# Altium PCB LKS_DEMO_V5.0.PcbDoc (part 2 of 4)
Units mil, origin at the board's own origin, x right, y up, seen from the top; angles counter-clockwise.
Board outline 5414.8 x 3354.56 mil, 2 copper layers (Top Layer, Bottom Layer); 131 components, 85 nets, 355 pads, 272 vias.
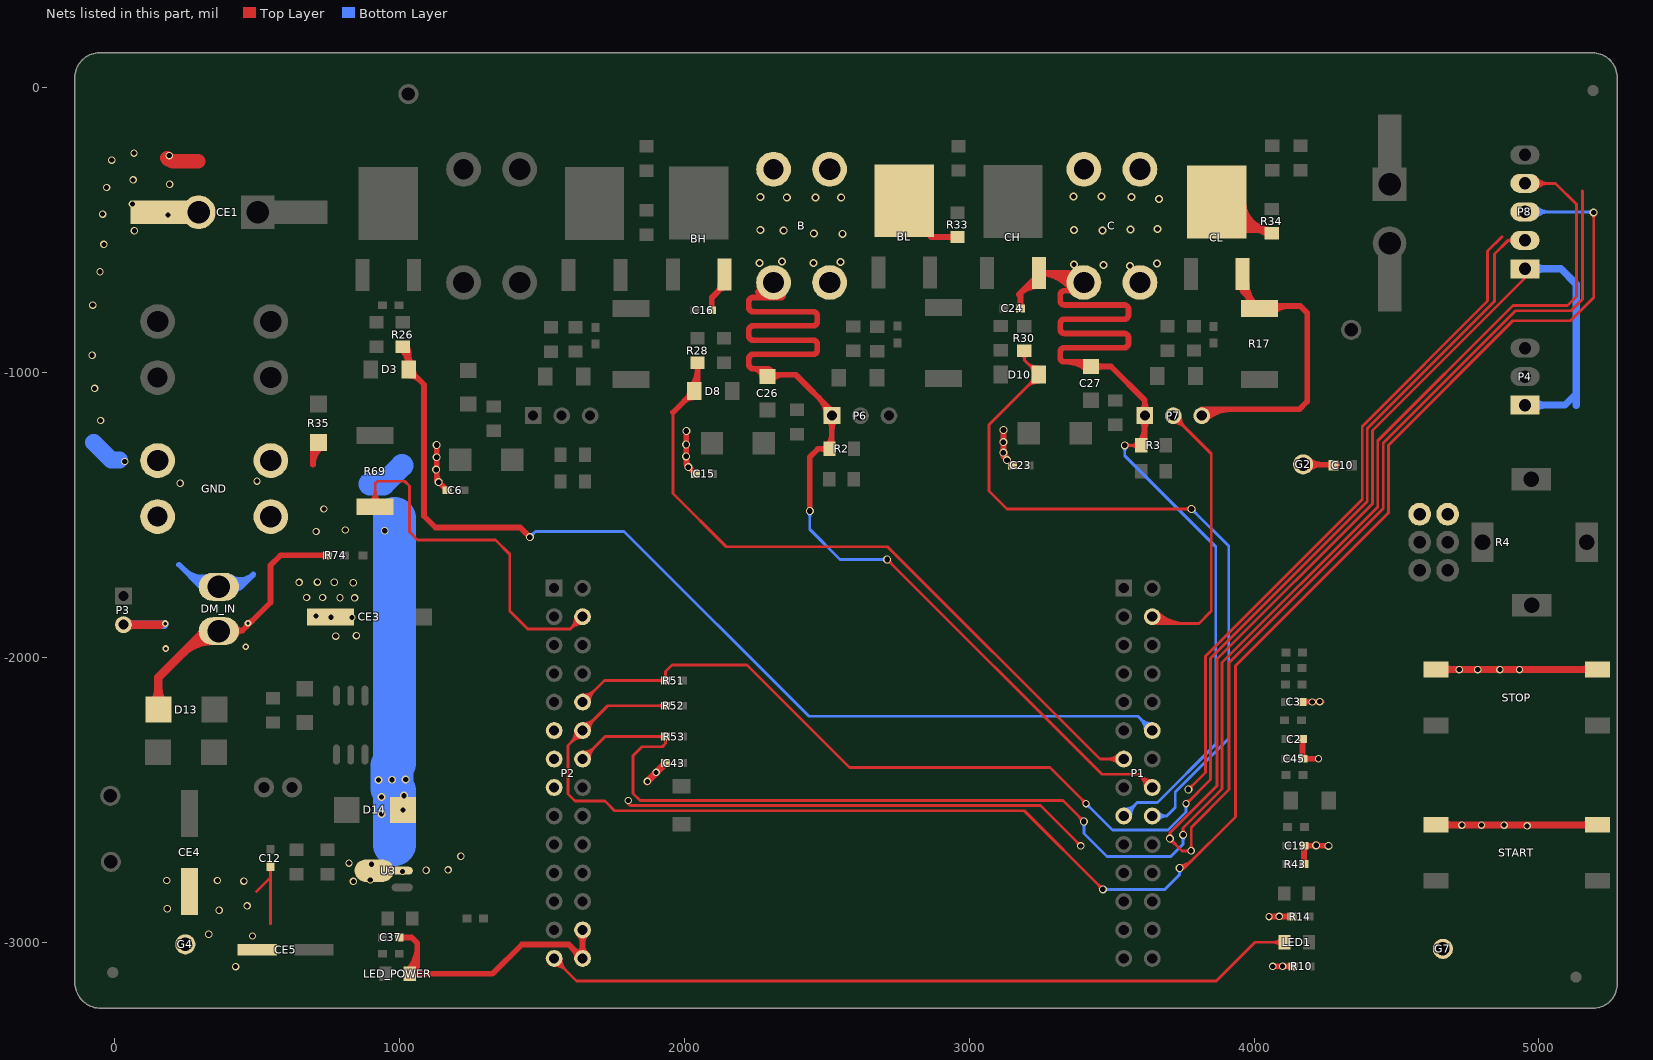
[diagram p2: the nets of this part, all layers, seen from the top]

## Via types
v1: diameter 26, hole 18, Top Layer to Bottom Layer, 117 vias
v2: diameter 28, hole 20, Top Layer to Bottom Layer, 77 vias
v3: diameter 28, hole 18, Top Layer to Bottom Layer, 73 vias
v4: diameter 23.62, hole 11.81, Top Layer to Bottom Layer, 5 vias

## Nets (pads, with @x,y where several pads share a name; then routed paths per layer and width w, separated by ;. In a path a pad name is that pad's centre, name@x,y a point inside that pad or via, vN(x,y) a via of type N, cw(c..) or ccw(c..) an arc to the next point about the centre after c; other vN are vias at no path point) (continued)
BX: B.1 BH.3 BL.2 C16.2 C26.2 P1.22 P6.1 R2.2 R33.2 | length 5651.7
  Top Layer w10: v2(2711.53,-1656.28) 3465.28,-2410.04 3595.47,-2410.04 P1.22@3642.25,-2456.82 ; 2726.89,-1671.64 ccw(c2711.53,-1687.01) 2711.53,-1665.28 cw(c2711.53,-1687.01) 2726.89,-1671.64 ; 2726.89,-1671.64 cw(c2742.25,-1656.28) 2720.53,-1656.28 ccw(c2742.25,-1656.28) 2726.89,-1671.64 ; 3600.38,-2414.94 ccw(c3642.25,-2373.07) 3642.25,-2432.29 cw(c3642.25,-2373.07) 3600.38,-2414.94 ; 3600.38,-2414.94 cw(c3558.51,-2456.82) 3617.72,-2456.82 ccw(c3558.51,-2456.82) 3600.38,-2414.94 ; 3617.45,-2432.02 ccw(c3642.25,-2407.22) 3642.25,-2442.29 cw(c3642.25,-2407.22) 3617.45,-2432.02 ; 3617.45,-2432.02 cw(c3592.65,-2456.82) 3627.72,-2456.82 ccw(c3592.65,-2456.82) 3617.45,-2432.02
  Top Layer w20: C16.2@2095.76,-779.93 2095.76,-737.17 BH.3@2142.44,-690.49 ; 2256.72,-716.82 2275.97,-736.07 ; C26.2@2283.73,-1030.78 2306.96,-1007.55 2390.76,-1007.55 2517.75,-1134.54 P6.1@2517.75,-1146.43 ; C26.2@2292.27,-1001.77 2276.58,-986.07 2240.96,-986.07 ; B.1@2345.96,-729.82 cw(c2339.71,-729.82) 2339.71,-736.07 2275.97,-736.07 ; v2(2439.84,-1486.25) 2439.84,-1296.61 2468.64,-1267.81 R2.2@2509.31,-1267.81 ; R2.2@2517.24,-1252.66 P6.1@2517.24,-1145.92 ; BL.2@2818.05,-476.55 2865.7,-524.2 R33.2@2958.78,-524.2 ; 2240.96,-986.07 cw(c2240.96,-971.07) 2225.96,-971.07 2225.96,-951.07 cw(c2240.96,-951.07) 2240.96,-936.07 2450.96,-936.07 ccw(c2450.96,-921.07) 2465.96,-921.07 2465.96,-901.07 ccw(c2450.96,-901.07) 2450.96,-886.07 2240.96,-886.07 cw(c2240.96,-871.07) 2225.96,-871.07 2225.96,-851.07 cw(c2240.96,-851.07) 2240.96,-836.07 2450.96,-836.07 ccw(c2450.96,-821.07) 2465.96,-821.07 2465.96,-801.07 ccw(c2450.96,-801.07) 2450.96,-786.07 2240.96,-786.07 cw(c2240.96,-771.07) 2225.96,-771.07 2225.96,-751.07 cw(c2240.96,-751.07) 2240.96,-736.07 2275.97,-736.07 ; 2240.96,-986.07 cw(c2240.96,-1018.55) 2273.27,-1015.24 ccw(c2240.96,-1018.55) 2240.96,-986.07 ; 2481.18,-1267.81 ccw(c2481.18,-1239.68) 2501.07,-1259.57 cw(c2481.18,-1239.68) 2481.18,-1267.81 ; 2481.18,-1267.81 cw(c2481.18,-1295.95) 2501.07,-1276.05 ccw(c2481.18,-1295.95) 2481.18,-1267.81 ; 2927.3,-524.2 ccw(c2927.3,-496.07) 2947.2,-515.96 cw(c2927.3,-496.07) 2927.3,-524.2 ; 2927.3,-524.2 cw(c2927.3,-552.33) 2947.2,-532.44 ccw(c2927.3,-552.33) 2927.3,-524.2 ; 2112.38,-720.55 ccw(c2079.48,-687.65) 2126.01,-687.65 cw(c2079.48,-687.65) 2112.38,-720.55 ; BH.3@2123.65,-709.29 cw(c2140.62,-726.26) 2140.62,-702.26 ccw(c2140.62,-726.26) BH.3@2123.65,-709.29 ; 2263.12,-986.07 cw(c2263.12,-1016.28) 2293.17,-1013.2 ccw(c2263.12,-1016.28) 2263.12,-986.07 ; 2285.27,-986.07 cw(c2285.27,-1014.01) 2313.06,-1011.16 ccw(c2285.27,-1014.01) 2285.27,-986.07 ; C26.2@2305.42,-1025.27 cw(c2348.2,-1068.06) 2348.2,-1007.55 ccw(c2348.2,-1068.06) C26.2@2305.42,-1025.27 ; 2472.61,-1089.39 cw(c2410.76,-1151.24) 2498.22,-1151.24 ccw(c2410.76,-1151.24) 2472.61,-1089.39 ; R2.2@2501.07,-1256.23 ccw(c2462.03,-1217.19) 2517.24,-1217.19 cw(c2462.03,-1217.19) R2.2@2501.07,-1256.23 ; P6.1@2503.94,-1165.05 cw(c2471.83,-1197.16) 2517.24,-1197.16 ccw(c2471.83,-1197.16) P6.1@2503.94,-1165.05 ; P6.1@2506.75,-1123.54 cw(c2479.05,-1151.24) 2518.22,-1151.24 ccw(c2479.05,-1151.24) P6.1@2506.75,-1123.54 ; 2517.24,-1199.61 cw(c2566.12,-1199.61) 2531.56,-1165.05 ccw(c2566.12,-1199.61) 2517.24,-1199.61
  Top Layer w30: BL.2@2771.14,-396.91 BL.2@2843.26,-324.79
  Bottom Layer w10: v2(2439.84,-1486.25) 2439.84,-1549.97 2546.15,-1656.28 v2(2711.53,-1656.28) ; 2439.84,-1507.98 ccw(c2418.11,-1507.98) 2433.48,-1492.61 cw(c2418.11,-1507.98) 2439.84,-1507.98 ; 2439.84,-1507.98 cw(c2461.57,-1507.98) 2446.2,-1492.61 ccw(c2461.57,-1507.98) 2439.84,-1507.98 ; 2689.8,-1656.28 ccw(c2689.8,-1634.55) 2705.16,-1649.92 cw(c2689.8,-1634.55) 2689.8,-1656.28 ; 2689.8,-1656.28 cw(c2689.8,-1678.01) 2705.16,-1662.64 ccw(c2689.8,-1678.01) 2689.8,-1656.28
  other v3: 2453.04,-615.74 2262.77,-614.91 2548.36,-611.49 2341.84,-609.97 2554.35,-512.78 2453.86,-511.13 2348.43,-501.25 2266.06,-499.6 2359.14,-385.93 2459.63,-385.11 2550.23,-385.11 2266.06,-383.46
CI: CL.3 P7.3 R17.1 | length 1960.4
  Top Layer w20: P7.3@3816.05,-1129.25 4158.12,-1129.25 4185.85,-1101.52 4185.85,-790.19 4161.78,-766.12 R17.1@4035,-766.12 ; CL.3@3959.59,-653.34 3959.59,-714.63 ; R17.1@4018.89,-773.93 3959.59,-714.63 ; CL.3@3950.65,-696.38 cw(c3936.51,-714.63) 3959.59,-714.63 ; CL.3@3950.65,-696.38 cw(c3936.51,-714.63) 3959.59,-714.63 ; CL.3@3950.65,-696.38 cw(c3936.51,-714.63) 3959.59,-714.63 ; CL.3@3950.65,-696.38 cw(c3936.51,-714.63) 3959.59,-714.63 ; 3959.59,-714.63 cw(c3982.67,-714.63) CL.3@3968.54,-696.38 ; 3959.59,-714.63 cw(c3982.67,-714.63) CL.3@3968.54,-696.38 ; 3959.59,-714.63 cw(c3982.67,-714.63) CL.3@3968.54,-696.38 ; 3959.59,-714.63 cw(c3982.67,-714.63) CL.3@3968.54,-696.38 ; P7.3@3815.72,-1150.9 cw(c3867.98,-1203.17) 3867.98,-1129.25 ccw(c3867.98,-1203.17) P7.3@3815.72,-1150.9 ; P7.3@3829.86,-1165.05 cw(c3916.27,-1251.46) 3916.27,-1129.25 ccw(c3916.27,-1251.46) P7.3@3829.86,-1165.05 ; CL.3@3954.2,-684.73 ccw(c4010.73,-685.8) 3970.75,-725.78 cw(c4010.73,-685.8) CL.3@3954.2,-684.73 ; 3968.31,-723.35 cw(c3927.85,-763.81) 3984.04,-774.61 ccw(c3927.85,-763.81) 3968.31,-723.35 ; CL.3@3974.2,-685.11 ccw(c4075.98,-687.04) 4003.99,-759.03 cw(c4075.98,-687.04) CL.3@3974.2,-685.11 ; R17.1@4068.26,-788.33 cw(c4121.87,-841.94) 4121.87,-766.12 ccw(c4121.87,-841.94) R17.1@4068.26,-788.33
CP: P1.16 P7.2 | length 2028.1
  Top Layer w10: P1.16@3642.25,-1856.82 3666.39,-1880.96 3806.07,-1880.96 3849.41,-1837.62 3849.41,-1284.87 3716.05,-1151.52 P7.2@3716.05,-1129.25 ; P1.16@3631.31,-1867.76 ccw(c3663.18,-1835.89) 3663.18,-1880.96 cw(c3663.18,-1835.89) P1.16@3631.31,-1867.76 ; P1.16@3638.38,-1860.69 ccw(c3687.32,-1811.75) 3687.32,-1880.96 cw(c3687.32,-1811.75) P1.16@3638.38,-1860.69 ; P1.16@3645.45,-1853.61 ccw(c3711.46,-1787.6) 3711.46,-1880.96 cw(c3711.46,-1787.6) P1.16@3645.45,-1853.61 ; P1.16@3652.52,-1846.54 ccw(c3735.6,-1763.46) 3735.6,-1880.96 cw(c3735.6,-1763.46) P1.16@3652.52,-1846.54 ; P1.16@3659.59,-1839.47 ccw(c3759.75,-1739.32) 3759.75,-1880.96 cw(c3759.75,-1739.32) P1.16@3659.59,-1839.47 ; P7.2@3716.05,-1175.77 cw(c3716.05,-1234.31) 3757.45,-1192.91 ccw(c3716.05,-1234.31) P7.2@3716.05,-1175.77 ; P7.2@3716.05,-1165.77 cw(c3716.05,-1200.16) 3740.37,-1175.84 ccw(c3716.05,-1200.16) P7.2@3716.05,-1165.77 ; P7.2@3730.58,-1151.24 ccw(c3766.32,-1151.24) 3741.05,-1176.51 cw(c3766.32,-1151.24) P7.2@3730.58,-1151.24 ; P7.2@3740.58,-1151.24 ccw(c3800.47,-1151.24) 3758.12,-1193.59 cw(c3800.47,-1151.24) P7.2@3740.58,-1151.24
CX: C24.2 C27.2 C.1 CH.3 CL.2 P1.9 P7.1 R3.2 R34.2 | length 7899.2
  Top Layer w10: v2@3545.76,-1255.52 R3.2@3603.88,-1255.52 ; 3563.68,-1255.52 ccw(c3563.68,-1215.31) 3592.11,-1243.74 cw(c3563.68,-1215.31) 3563.68,-1255.52 ; 3563.68,-1255.52 cw(c3563.68,-1295.72) 3592.11,-1267.29 ccw(c3563.68,-1295.72) 3563.68,-1255.52 ; v2@3552.04,-1261.8 cw(c3567.2,-1276.96) 3567.2,-1255.52 ccw(c3567.2,-1276.96) v2@3552.04,-1261.8 ; v2@3552.04,-1249.07 ccw(c3567.6,-1233.51) 3567.6,-1255.52 cw(c3567.6,-1233.51) v2@3552.04,-1249.07
  Top Layer w20: C24.2@3179.62,-774.76 3179.62,-719.71 CH.3@3244.29,-655.03 ; C.1@3407.81,-708.51 3350.03,-650.72 CH.3@3243.88,-650.72 ; C27.2@3427.06,-978.99 3497.71,-978.99 3616.05,-1097.32 P7.1@3616.05,-1151.24 ; C27.2@3431.28,-962.46 3334.05,-962.46 cw(c3334.05,-947.46) 3319.05,-947.46 3319.05,-927.46 cw(c3334.05,-927.46) 3334.05,-912.46 3544.05,-912.46 ccw(c3544.05,-897.46) 3559.05,-897.46 3559.05,-877.46 ccw(c3544.05,-877.46) 3544.05,-862.46 3334.05,-862.46 cw(c3334.05,-847.46) 3319.05,-847.46 3319.05,-827.46 cw(c3334.05,-827.46) 3334.05,-812.46 3544.05,-812.46 ccw(c3544.05,-797.46) 3559.05,-797.46 3559.05,-777.46 ccw(c3544.05,-777.46) 3544.05,-762.46 3334.05,-762.46 cw(c3334.05,-747.46) 3319.05,-747.46 3319.05,-727.46 cw(c3334.05,-727.46) 3334.05,-712.46 3430.58,-712.46 ccw(c3430.58,-704) C.1@3439.04,-704 ; R3.2@3614.91,-1254.73 P7.1@3614.91,-1128.61 ; CL.2@3869.04,-401.37 3967.82,-500.15 R34.2@4064.65,-500.15 ; CH.3@3243.88,-650.72 cw(c3243.89,-790.89) 3360,-712.38 ccw(c3243.89,-790.89) CH.3@3243.88,-650.72 ; 3279.14,-650.72 ccw(c3279.14,-685.99) 3254.21,-661.05 cw(c3279.14,-685.99) 3279.14,-650.72 ; 3279.14,-650.72 cw(c3279.14,-615.46) 3254.21,-640.4 ccw(c3279.14,-615.46) 3279.14,-650.72 ; 3469.04,-978.99 ccw(c3469.04,-1019) 3440.74,-990.71 cw(c3469.04,-1019) 3469.04,-978.99 ; 3469.04,-978.99 cw(c3469.04,-938.97) 3440.74,-967.27 ccw(c3469.04,-938.97) 3469.04,-978.99 ; 3616.05,-1104.09 ccw(c3663.19,-1104.09) 3629.86,-1137.43 cw(c3663.19,-1104.09) 3616.05,-1104.09 ; 3616.05,-1104.09 cw(c3568.91,-1104.09) 3602.24,-1137.43 ccw(c3568.91,-1104.09) 3616.05,-1104.09 ; R34.2@4064.64,-500.15 cw(c4064.64,-396.87) 3962.41,-411.57 ccw(c4064.64,-396.87) R34.2@4064.64,-500.15 ; 3173.24,-726.09 cw(c3243.88,-796.73) 3243.88,-696.83 ccw(c3243.88,-796.73) 3173.24,-726.09 ; 3207.38,-691.95 cw(c3243.88,-728.45) 3243.88,-676.83 ccw(c3243.88,-728.45) 3207.38,-691.95 ; CH.3@3241.52,-657.8 cw(c3243.88,-660.16) 3243.88,-656.83 ccw(c3243.88,-660.16) CH.3@3241.52,-657.8 ; 3281.56,-650.72 cw(c3281.56,-765.42) 3376.57,-701.17 ccw(c3281.56,-765.42) 3281.56,-650.72 ; 3319.22,-650.72 cw(c3319.22,-739.95) 3393.14,-689.97 ccw(c3319.22,-739.95) 3319.22,-650.72 ; 3345.18,-962.46 cw(c3345.18,-1058.9) 3413.37,-990.71 ccw(c3345.18,-1058.9) 3345.18,-962.46 ; 3348.3,-712.46 cw(c3348.3,-737.77) 3366.19,-719.87 ccw(c3348.3,-737.77) 3348.3,-712.46 ; 3393.46,-962.46 cw(c3393.46,-1010.61) 3427.51,-976.57 ccw(c3393.46,-1010.61) 3393.46,-962.46 ; R3.2@3595.64,-1243.93 ccw(c3549.14,-1197.43) 3614.91,-1197.43 cw(c3549.14,-1197.43) R3.2@3595.64,-1243.93 ; P7.1@3602.24,-1165.05 cw(c3571.67,-1195.62) 3614.91,-1195.62 ccw(c3571.67,-1195.62) P7.1@3602.24,-1165.05 ; 3614.91,-1201.15 cw(c3665.96,-1201.15) 3629.86,-1165.05 ccw(c3665.96,-1201.15) 3614.91,-1201.15 ; CL.2@3883.23,-422.95 ccw(c3972.32,-410.14) 3972.32,-500.15 cw(c3972.32,-410.14) CL.2@3883.23,-422.95 ; CL.2@3903.02,-420.1 ccw(c3995.4,-406.82) 3995.4,-500.15 cw(c3995.4,-406.82) CL.2@3903.02,-420.1 ; CL.2@3922.82,-417.26 ccw(c4018.48,-403.5) 4018.48,-500.15 cw(c4018.48,-403.5) CL.2@3922.82,-417.26 ; CL.2@3942.61,-414.41 ccw(c4041.56,-400.18) 4041.56,-500.15 cw(c4041.56,-400.18) CL.2@3942.61,-414.41 ; 4003.57,-500.15 cw(c4003.57,-566.15) 4050.23,-519.48 ccw(c4003.57,-566.15) 4003.57,-500.15
  Bottom Layer w10: P1.9@3542.25,-2556.82 3589.53,-2509.53 3660.12,-2509.53 3865.01,-2304.65 3865.01,-1611.21 3545.66,-1291.87 v2@3545.66,-1255.42 ; 3567.05,-2532.02 ccw(c3591.85,-2556.82) 3556.78,-2556.82 cw(c3591.85,-2556.82) 3567.05,-2532.02 ; 3567.05,-2532.02 cw(c3542.25,-2507.22) 3542.25,-2542.29 ccw(c3542.25,-2507.22) 3567.05,-2532.02 ; 3584.12,-2514.94 ccw(c3625.99,-2556.82) 3566.78,-2556.82 cw(c3625.99,-2556.82) 3584.12,-2514.94 ; 3584.12,-2514.94 cw(c3542.25,-2473.07) 3542.25,-2532.29 ccw(c3542.25,-2473.07) 3584.12,-2514.94 ; v2@3539.31,-1261.8 cw(c3523.97,-1277.14) 3545.66,-1277.14 ccw(c3523.97,-1277.14) v2@3539.31,-1261.8 ; 3545.66,-1277.18 cw(c3567.42,-1277.18) 3552.04,-1261.8 ccw(c3567.42,-1277.18) 3545.66,-1277.18
  other v2: 3545.67,-1255.43
  other v3: 3564.36,-625.82 3471.16,-622.37 3367.61,-620.65 3658.66,-616.83 3467.71,-501.56 3367.61,-499.84 3566.09,-498.11 3661.01,-496.39 3666.19,-391.11 3569.54,-384.21 3365.89,-382.48 3464.26,-382.48
DM_IN: D13.1 DM_IN.1 P3.2 R74.1 | length 2236.4
  Top Layer w20: DM_IN.1@316.98,-1905.81 447.95,-1905.81 ; R74.1@746.62,-1641.8 581.53,-1641.8 546.73,-1676.6 546.73,-1807.04 447.95,-1905.81 ; 447.95,-1905.81 ccw(c447.95,-1932.18) 423.45,-1922.44 cw(c447.95,-1932.18) 447.95,-1905.81 ; 447.95,-1905.81 cw(c447.95,-1876.37) 421.82,-1889.92 ccw(c447.95,-1876.37) 447.95,-1905.81 ; 460.08,-1893.69 ccw(c446.31,-1879.92) 465.78,-1879.92 cw(c446.31,-1879.92) 460.08,-1893.69 ; v4@467.59,-1878.11 ccw(c467.59,-1858.64) 481.36,-1872.41 cw(c467.59,-1858.64) v4@467.59,-1878.11
  Top Layer w30: P3.2@30.28,-1884.94 160,-1884.94 ; D13.1@153,-2182.97 153,-2069.8 DM_IN.1@316.98,-1905.81 ; 65.35,-1884.94 ccw(c65.35,-1920.01) 40.55,-1895.21 cw(c65.35,-1920.01) 65.35,-1884.94 ; 65.35,-1884.94 cw(c65.35,-1849.87) 40.55,-1874.67 ccw(c65.35,-1849.87) 65.35,-1884.94 ; 153,-2109.88 ccw(c226.09,-2109.88) 174.4,-2161.56 cw(c226.09,-2109.88) 153,-2109.88 ; 153,-2109.88 cw(c79.9,-2109.88) 131.59,-2161.56 ccw(c79.9,-2109.88) 153,-2109.88 ; 236,-1986.79 cw(c343.7,-2094.48) 343.7,-1942.18 ccw(c343.7,-2094.48) 236,-1986.79 ; 287.22,-1935.57 cw(c343.7,-1992.05) 343.7,-1912.18 ccw(c343.7,-1992.05) 287.22,-1935.57
  Bottom Layer w30: P3.2@30.28,-1884.94 v4@173.43,-1884.94 ; 65.35,-1884.94 ccw(c65.35,-1920.01) 40.55,-1895.21 cw(c65.35,-1920.01) 65.35,-1884.94 ; 65.35,-1884.94 cw(c65.35,-1849.87) 40.55,-1874.67 ccw(c65.35,-1849.87) 65.35,-1884.94
  other v4: 178.44,-1968.99 459.85,-1962.53 177.15,-1881.21 467.59,-1879.92
GND: C2.1 C3.2 C6.1 C10.2 C12.2 C15.1 C19.1 C23.1 C37.1 C43.1 C45.1 CE1.2 CE3.2 CE4.2 CE5.2 D14.1 DM_IN.2 G2.1 G4.1 G7.1 GND.1 LED_POWER.2 P2.16 P2.27 P2.28 P4.1 P8.1 R4.2 R4.4 R10.2 R14.2 R35.2 R43.1 R69.2 START.1 START.3 STOP.1 STOP.3 U3.2 | length 24932.8
  Top Layer w10: 497.13,-2822.29 546.38,-2773.05 ; 546.38,-2934.9 C12.2@546.38,-2734.12 ; R69.2@914.27,-1470.9 914.27,-1389.58 922.35,-1381.5 1017.63,-1381.5 1034.22,-1398.09 1034.22,-1558.82 1062.7,-1587.3 1336.01,-1587.3 1386.69,-1637.98 1386.69,-1836.74 1449.85,-1899.9 1599.17,-1899.9 P2.16@1642.25,-1856.82 ; v1(1802.37,-2502.34) 1802.37,-2513.52 1809.13,-2520.28 3249.96,-2520.28 v1@3391.58,-2661.9 ; v2(3768.98,-2463.96) 3829.09,-2403.83 3829.09,-1995.77 4379.28,-1445.58 4379.28,-1188.95 4819.78,-748.44 4819.78,-573.14 4870.02,-522.9 ; v1@3776.66,-2679.5 3746.72,-2679.5 v2(3703.71,-2636.48) 3703.7,-2616.34 ; v1@3779.38,-2682.22 3779.38,-2596.62 3911.8,-2464.2 3911.8,-2018.96 4453.19,-1477.57 4453.19,-1247.54 4917.92,-782.81 5112.33,-782.81 5152.47,-742.68 5152.47,-363.2 5151.94,-362.68 ; P8.1@4950.7,-635.64 4950.7,-668.08 4415.03,-1203.76 4415.03,-1460.39 3869.28,-2006.13 3869.28,-2450.75 3703.7,-2616.34 ; 546.38,-2757.28 ccw(c525.18,-2757.28) 540.17,-2742.29 cw(c525.18,-2757.28) 546.38,-2757.28 ; 546.38,-2757.28 cw(c567.57,-2757.28) 552.58,-2742.29 ccw(c567.57,-2757.28) 546.38,-2757.28 ; 914.27,-1435.82 ccw(c949.34,-1435.82) 924.54,-1460.62 cw(c949.34,-1435.82) 914.27,-1435.82 ; 914.27,-1435.82 cw(c879.2,-1435.82) 904,-1460.62 ccw(c879.2,-1435.82) 914.27,-1435.82 ; 914.27,-1411.68 ccw(c973.49,-1411.68) 931.61,-1453.55 cw(c973.49,-1411.68) 914.27,-1411.68 ; 914.27,-1411.68 cw(c855.06,-1411.68) 896.93,-1453.55 ccw(c855.06,-1411.68) 914.27,-1411.68 ; 1600.38,-1898.69 ccw(c1558.51,-1856.82) 1617.72,-1856.82 cw(c1558.51,-1856.82) 1600.38,-1898.69 ; 1600.38,-1898.69 cw(c1642.25,-1940.56) 1642.25,-1881.34 ccw(c1642.25,-1940.56) 1600.38,-1898.69 ; 1617.45,-1881.62 ccw(c1592.65,-1856.82) 1627.72,-1856.82 cw(c1592.65,-1856.82) 1617.45,-1881.62 ; 1617.45,-1881.62 cw(c1642.25,-1906.42) 1642.25,-1871.34 ccw(c1642.25,-1906.42) 1617.45,-1881.62 ; 3703.7,-2616.34 ccw(c3721.72,-2616.34) 3709.71,-2629.78 cw(c3721.72,-2616.34) 3703.7,-2616.34 ; 3703.7,-2616.34 cw(c3685.64,-2616.34) 3697.7,-2629.78 ccw(c3685.64,-2616.34) 3703.7,-2616.34 ; 3719.07,-2651.85 ccw(c3703.71,-2667.21) 3703.71,-2645.48 cw(c3703.71,-2667.21) 3719.07,-2651.85 ; 3719.07,-2651.85 cw(c3734.43,-2636.48) 3712.71,-2636.48 ccw(c3734.43,-2636.48) 3719.07,-2651.85 ; v1@3773.01,-2673.08 cw(c3757.51,-2657.58) 3757.51,-2679.5 ccw(c3757.51,-2657.58) v1@3773.01,-2673.08 ; v1@3773.01,-2673.08 ccw(c3757.64,-2657.71) 3779.38,-2657.71 cw(c3757.64,-2657.71) v1@3773.01,-2673.08 ; 3376.88,-2647.21 cw(c3362.19,-2661.9) 3382.97,-2661.9 ccw(c3362.19,-2661.9) 3376.88,-2647.21 ; 3378.36,-2648.68 ccw(c3390.97,-2636.06) 3390.97,-2653.9 cw(c3390.97,-2636.06) 3378.36,-2648.68 ; 3761.2,-2679.5 cw(c3761.2,-2696.21) 3773.01,-2684.39 ccw(c3761.2,-2696.21) 3761.2,-2679.5 ; v2@3768.98,-2454.96 ccw(c3768.98,-2433.27) 3784.32,-2448.6 cw(c3768.98,-2433.27) v2@3768.98,-2454.96 ; v2@3777.98,-2463.96 cw(c3799.75,-2463.96) 3784.36,-2448.56 ccw(c3799.75,-2463.96) v2@3777.98,-2463.96 ; 3779.38,-2661.14 ccw(c3796.27,-2661.14) 3784.33,-2673.08 cw(c3796.27,-2661.14) 3779.38,-2661.14
  Top Layer w20: 695.87,-1320.57 695.87,-1264.91 R35.2@715.63,-1245.14 ; C37.1@998.61,-2983.24 1042.18,-2983.24 1061.93,-3002.99 1061.93,-3084.89 LED_POWER.2@1036.01,-3110.82 1326.22,-3110.82 1429.02,-3008.01 1593.45,-3008.01 P2.28@1642.25,-3056.82 P2.27@1642.25,-2956.82 ; v2(1129.78,-1254.51) 1129.77,-1376.63 C6.1@1166.15,-1413.01 ; v2@2006.32,-1205.37 2006.32,-1322.72 C15.1@2039.42,-1355.82 ; v2(3120.2,-1201.76) 3120.19,-1294.77 C23.1@3151.34,-1325.92 ; v1(4052.23,-2909.82) R14.2@4132.95,-2909.82 ; v1(4065.25,-3084.6) R10.2@4136.85,-3084.6 ; C3.2@4168.4,-2156.04 v1@4236.85,-2156.04 ; C45.1@4170.04,-2355.01 C2.1@4170.04,-2286.71 ; C45.1@4170.76,-2355.72 v1(4225.95,-2355.72) ; G2.1@4171.95,-1322.36 4172.91,-1323.32 C10.2@4291.96,-1323.32 ; R43.1@4174.8,-2725.21 C19.1@4174.8,-2661.32 v2(4260.7,-2661.32) ; R35.2@715.63,-1245.14 ccw(c743.75,-1283.9) 695.87,-1283.9 cw(c743.75,-1283.9) R35.2@715.63,-1245.14 ; 1064.14,-3110.82 ccw(c1064.14,-3138.95) 1044.25,-3119.06 cw(c1064.14,-3138.95) 1064.14,-3110.82 ; 1064.14,-3110.82 cw(c1064.14,-3082.68) 1044.25,-3102.58 ccw(c1064.14,-3082.68) 1064.14,-3110.82 ; 1608.91,-3023.48 ccw(c1642.25,-2990.14) 1642.25,-3037.29 cw(c1642.25,-2990.14) 1608.91,-3023.48 ; 1608.91,-3023.48 cw(c1575.58,-3056.82) 1622.72,-3056.82 ccw(c1575.58,-3056.82) 1608.91,-3023.48 ; 1642.25,-3009.67 ccw(c1689.39,-3009.67) 1656.06,-3043.01 cw(c1689.39,-3009.67) 1642.25,-3009.67 ; 1642.25,-3009.67 cw(c1595.11,-3009.67) 1628.44,-3043.01 ccw(c1595.11,-3009.67) 1642.25,-3009.67 ; 1642.25,-3003.96 ccw(c1595.11,-3003.96) 1628.44,-2970.62 cw(c1595.11,-3003.96) 1642.25,-3003.96 ; 1642.25,-3003.96 cw(c1689.39,-3003.96) 1656.06,-2970.62 ccw(c1689.39,-3003.96) 1642.25,-3003.96 ; 695.87,-1323.12 cw(c772.21,-1323.12) 727.38,-1261.33 ccw(c772.21,-1323.12) 695.87,-1323.12 ; LED_POWER.2@1027.77,-3099.23 ccw(c945.28,-3016.75) 1061.93,-3016.75 cw(c945.28,-3016.75) LED_POWER.2@1027.77,-3099.23 ; LED_POWER.2@1036.01,-3095.82 ccw(c1036.01,-3059.61) 1061.62,-3085.21 cw(c1036.01,-3059.61) LED_POWER.2@1036.01,-3095.82 ; LED_POWER.2@1041.91,-3113.37 ccw(c993.57,-3065.03) 1061.93,-3065.03 cw(c993.57,-3065.03) LED_POWER.2@1041.91,-3113.37 ; LED_POWER.2@1047.66,-3107.47 cw(c1067.72,-3107.47) 1053.54,-3093.29 ccw(c1067.72,-3107.47) LED_POWER.2@1047.66,-3107.47 ; 1129.77,-1357.32 ccw(c1164.29,-1357.32) 1139.88,-1381.73 cw(c1164.29,-1357.32) 1129.77,-1357.32 ; v2@2006.32,-1305.48 ccw(c2039.73,-1305.48) 2016.1,-1329.11 cw(c2039.73,-1305.48) v2@2006.32,-1305.48 ; v2@3120.19,-1268.51 ccw(c3171.41,-1268.51) 3135.19,-1304.73 cw(c3171.41,-1268.51) v2@3120.19,-1268.51 ; v2@3123.43,-1281.22 ccw(c3163.96,-1281.22) 3135.3,-1309.88 cw(c3163.96,-1281.22) v2@3123.43,-1281.22 ; G2.1@4189.94,-1340.35 cw(c4231.04,-1381.45) 4231.04,-1323.32 ccw(c4231.04,-1381.45) G2.1@4189.94,-1340.35 ; G2.1@4189.94,-1304.38 ccw(c4235.67,-1258.65) 4235.67,-1323.32 cw(c4235.67,-1258.65) G2.1@4189.94,-1304.38 ; 4203.73,-2661.32 ccw(c4203.73,-2645.65) 4214.81,-2656.73 cw(c4203.73,-2645.65) 4203.73,-2661.32 ; v2@4220.47,-2656.73 ccw(c4231.55,-2645.65) 4231.55,-2661.32 cw(c4231.55,-2645.65) v2@4220.47,-2656.73 ; 4256.74,-1323.32 cw(c4256.74,-1346.44) 4273.09,-1330.1 ccw(c4256.74,-1346.44) 4256.74,-1323.32
  Top Layer w25: v1@1868.24,-2436.71 C43.1@1933.69,-2371.26 ; START.1@4617.02,-2588.57 4753.42,-2588.57 START.3@5183.94,-2588.58 ; STOP.1@4617.02,-2042.15 STOP.3@5183.95,-2042.15 ; v1@4720.17,-2042.15 STOP.3@5183.95,-2042.15 ; v1@4785.1,-2042.15 STOP.3@5183.95,-2042.15 ; v1@4798.13,-2588.58 START.3@5183.94,-2588.58 ; v1@4862.87,-2042.15 STOP.3@5183.95,-2042.15 ; v1@4877.34,-2588.58 START.3@5183.94,-2588.58 ; v1@4931.39,-2042.15 STOP.3@5183.95,-2042.15 ; v1@4958.33,-2588.58 START.3@5183.94,-2588.58 ; 5150.18,-2588.58 ccw(c5150.18,-2547.57) START.3@5179.17,-2576.57 ; 5150.18,-2588.58 ccw(c5150.18,-2547.57) START.3@5179.17,-2576.57 ; 5150.18,-2588.58 ccw(c5150.18,-2547.57) START.3@5179.17,-2576.57 ; 5150.18,-2588.58 ccw(c5150.18,-2547.57) START.3@5179.17,-2576.57 ; 5150.18,-2588.58 ccw(c5150.18,-2547.57) START.3@5179.17,-2576.57 ; 5150.18,-2588.58 ccw(c5150.18,-2547.57) START.3@5179.17,-2576.57 ; 5150.18,-2588.58 ccw(c5150.18,-2547.57) START.3@5179.17,-2576.57 ; 5150.18,-2588.58 ccw(c5150.18,-2547.57) START.3@5179.17,-2576.57 ; 5153.14,-2042.15 cw(c5153.14,-2078.97) STOP.3@5179.17,-2052.93 ; 5153.14,-2042.15 cw(c5153.14,-2078.97) STOP.3@5179.17,-2052.93 ; 5153.14,-2042.15 cw(c5153.14,-2078.97) STOP.3@5179.17,-2052.93 ; 5153.14,-2042.15 cw(c5153.14,-2078.97) STOP.3@5179.17,-2052.93 ; 5153.14,-2042.15 cw(c5153.14,-2078.97) STOP.3@5179.17,-2052.93 ; 5153.14,-2042.15 cw(c5153.14,-2078.97) STOP.3@5179.17,-2052.93 ; 5153.14,-2042.15 cw(c5153.14,-2078.97) STOP.3@5179.17,-2052.93 ; 5153.14,-2042.15 cw(c5153.14,-2078.97) STOP.3@5179.17,-2052.93 ; 5153.14,-2042.15 cw(c5153.14,-2078.97) STOP.3@5179.17,-2052.93 ; 5153.14,-2042.15 cw(c5153.14,-2078.97) STOP.3@5179.17,-2052.93 ; 5154,-2042.15 ccw(c5154,-2006.55) STOP.3@5179.17,-2031.72 ; 5154,-2042.15 ccw(c5154,-2006.55) STOP.3@5179.17,-2031.72 ; 5154,-2042.15 ccw(c5154,-2006.55) STOP.3@5179.17,-2031.72 ; 5154,-2042.15 ccw(c5154,-2006.55) STOP.3@5179.17,-2031.72 ; 5154,-2042.15 ccw(c5154,-2006.55) STOP.3@5179.17,-2031.72 ; 5154,-2042.15 ccw(c5154,-2006.55) STOP.3@5179.17,-2031.72 ; 5154,-2042.15 ccw(c5154,-2006.55) STOP.3@5179.17,-2031.72 ; 5154,-2042.15 ccw(c5154,-2006.55) STOP.3@5179.17,-2031.72 ; 5154,-2042.15 ccw(c5154,-2006.55) STOP.3@5179.17,-2031.72 ; 5154,-2042.15 ccw(c5154,-2006.55) STOP.3@5179.17,-2031.72 ; 5156.96,-2588.58 cw(c5156.96,-2620) START.3@5179.17,-2597.78 ; 5156.96,-2588.58 cw(c5156.96,-2620) START.3@5179.17,-2597.78 ; 5156.96,-2588.58 cw(c5156.96,-2620) START.3@5179.17,-2597.78 ; 5156.96,-2588.58 cw(c5156.96,-2620) START.3@5179.17,-2597.78 ; 5156.96,-2588.58 cw(c5156.96,-2620) START.3@5179.17,-2597.78 ; 5156.96,-2588.58 cw(c5156.96,-2620) START.3@5179.17,-2597.78 ; 5156.96,-2588.58 cw(c5156.96,-2620) START.3@5179.17,-2597.78 ; 5156.96,-2588.58 cw(c5156.96,-2620) START.3@5179.17,-2597.78 ; START.1@4665.07,-2597.78 cw(c4687.31,-2620.02) 4687.31,-2588.57 ccw(c4687.31,-2620.02) START.1@4665.07,-2597.78 ; START.1@4665.07,-2576.57 ccw(c4694.05,-2547.59) 4694.05,-2588.57 cw(c4694.05,-2547.59) START.1@4665.07,-2576.57 ; STOP.1@4665.07,-2052.93 cw(c4691.11,-2078.97) 4691.11,-2042.15 ccw(c4691.11,-2078.97) STOP.1@4665.07,-2052.93 ; STOP.1@4665.07,-2031.72 ccw(c4690.25,-2006.55) 4690.25,-2042.15 cw(c4690.25,-2006.55) STOP.1@4665.07,-2031.72
  Top Layer w50: 219.27,-258.2 292.97,-258.2 ; v1@182.84,-246.99 ccw(c209.92,-219.91) 209.92,-258.2 ; v1@182.84,-246.99 ccw(c209.92,-219.91) 209.92,-258.2 ; v1@182.84,-246.99 ccw(c209.92,-219.91) 209.92,-258.2 ; v1@182.84,-246.99 ccw(c209.92,-219.91) 209.92,-258.2
  Bottom Layer w20: 225.47,-1674.17 303.37,-1752.06 DM_IN.2@365.35,-1752.06 443.52,-1752.06 ; 486.46,-1708.31 486.46,-1709.13 ; 443.52,-1752.06 ccw(c443.52,-1773.18) 423.74,-1765.79 cw(c443.52,-1773.18) 443.52,-1752.06 ; 443.52,-1752.06 cw(c443.52,-1730.94) 423.74,-1738.34 ccw(c443.52,-1730.94) 443.52,-1752.06 ; 443.52,-1752.06 486.46,-1709.13 ; 486.45,-1709.13 cw(c440.92,-1663.6) 407.41,-1718.58 ccw(c440.92,-1663.6) 486.45,-1709.13 ; 245.64,-1694.33 ccw(c305.2,-1634.77) 331.47,-1714.81 cw(c305.2,-1634.77) 245.64,-1694.33 ; 268.64,-1717.33 ccw(c316.57,-1669.41) 337.71,-1733.81 cw(c316.57,-1669.41) 268.64,-1717.33 ; 291.64,-1740.34 ccw(c327.94,-1704.04) 343.94,-1752.81 cw(c327.94,-1704.04) 291.64,-1740.34 ; DM_IN.2@386.59,-1752.73 ccw(c413.68,-1708.29) 450.49,-1745.1 cw(c413.68,-1708.29) DM_IN.2@386.59,-1752.73 ; DM_IN.2@397,-1735.66 ccw(c427.3,-1685.95) 468.47,-1727.11 cw(c427.3,-1685.95) DM_IN.2@397,-1735.66
  Bottom Layer w25: P8.1@4950.7,-635.64 5076.7,-635.64 5130.71,-689.65 5130.71,-1116 ; P4.1@4950.98,-1114.16 5091.22,-1114.16 5129.77,-1075.61 ; 5019.03,-635.64 ccw(c5019.03,-686.25) 4983.24,-650.46 cw(c5019.03,-686.25) 5019.03,-635.64 ; 5019.03,-635.64 cw(c5019.03,-585.03) 4983.24,-620.81 ccw(c5019.03,-585.03) 5019.03,-635.64 ; 5019.31,-1114.16 ccw(c5019.31,-1164.77) 4983.52,-1128.98 cw(c5019.31,-1164.77) 5019.31,-1114.16 ; 5019.31,-1114.16 cw(c5019.31,-1063.55) 4983.52,-1099.34 ccw(c5019.31,-1063.55) 5019.31,-1114.16
  Bottom Layer w60: -74.04,-1245.5 -12.52,-1307.02 16.56,-1307.02
  Bottom Layer w80: 896.26,-1390.9 942.86,-1390.9 1007.94,-1325.82
  Bottom Layer w150: 973.1,-2380.58 973.1,-2459.15 982.12,-2468.17 982.12,-2657.27 ; 982.12,-2371.57 982.12,-1511.05
  other v1: 424.25,-3085.42 4099.94,-3084.46 483.5,-2977.96 329.85,-2971.94 4088.19,-2909.35 366,-2887.59 184.24,-2882.56 464.42,-2872.52 837.75,-2786.45 453.37,-2785.16 182.24,-2783.16 359.98,-2783.15 896.63,-2780.84 1010.18,-2751.4 1092.9,-2747.2 1170,-2745.8 900.83,-2726.17 822.33,-2721.97 1214.86,-2698.13 3778.67,-2678.74 3390.97,-2661.9 4958.33,-2591.38 4729.02,-2588.72 4798.13,-2588.72 4877.34,-2588.72 1869.87,-2435.22 1900.23,-2403.68 4204.03,-2156.43 4230.14,-2155.35 4720.17,-2043.04 4785.1,-2043.04 4862.87,-2043.03 4931.39,-2043.04 775.87,-1925.26 847.94,-1923.47 832.28,-1859.91 758.86,-1859.02 706.04,-1854.99 842.13,-1790.98 790.66,-1790.52 673.35,-1789.64 729.77,-1789.63 837.2,-1737.7 646.96,-1736.37 770.5,-1735.91 710.97,-1735.47 706.7,-1557.82 947.56,-1555.31 808.85,-1552.82 734.1,-1478.9 229.1,-1388.38 499.04,-1380.88 35.06,-1312.15 -49.76,-1168.18 -70.96,-1055.46 -79.9,-939.39 -77.66,-763.06 -51.99,-645.88 -38.6,-549.9 68.54,-501.9 186.85,-447.22 -43.06,-443.87 61.85,-408.16 -28.55,-350.12 192.43,-338.95 64.08,-323.34 -10.69,-254.14 191.33,-238.5 67.43,-229.59
  other v2: 4217.64,-2659.56 1137.05,-1384.56 1128.08,-1340.93 2013.27,-1331.94 3132.36,-1307.56 1130.11,-1297.3 2005.83,-1293.87 3119.43,-1281.22 2006.1,-1252.77 3119.42,-1244.25 2006.33,-1205.38
  other v3: 936.33,-2549.72 1011.33,-2535.22 936.33,-2490.22 1014.7,-2485.58 925.11,-2429.8 973.1,-2429.45 1021.33,-2428.4
HA: P2.21 P8.4 R53.1 | length 6877.8
  Top Layer w10: P2.21@1642.88,-2357.31 1722,-2278.19 R53.1@1933.69,-2278.19 1933.69,-2301.94 1921.83,-2313.79 1850.92,-2313.79 1819.65,-2345.06 1819.65,-2477.4 1844.66,-2502.4 3328.72,-2502.4 v2@3402.28,-2575.96 ; v2(3750.64,-2622.69) 3750.64,-2598.63 3887.15,-2462.12 3887.15,-2018.33 4433.99,-1471.49 4433.99,-1239.49 4908.54,-764.94 5100.14,-764.94 5131.81,-733.27 5131.81,-409.29 5058.15,-335.64 P8.4@4950.7,-335.64 ; 1910.53,-2278.19 ccw(c1910.53,-2257) 1925.52,-2271.98 cw(c1910.53,-2257) 1910.53,-2278.19 ; 1910.53,-2278.19 cw(c1910.53,-2299.39) 1925.52,-2284.4 ccw(c1910.53,-2299.39) 1910.53,-2278.19 ; 1933.69,-2299.39 ccw(c1912.5,-2299.39) 1927.48,-2284.4 cw(c1912.5,-2299.39) 1933.69,-2299.39 ; 1933.69,-2299.39 cw(c1954.89,-2299.39) 1939.9,-2284.4 ccw(c1954.89,-2299.39) 1933.69,-2299.39 ; 3750.64,-2600.96 ccw(c3772.37,-2600.96) 3757.01,-2616.32 cw(c3772.37,-2600.96) 3750.64,-2600.96 ; 3750.64,-2600.96 cw(c3728.91,-2600.96) 3744.28,-2616.32 ccw(c3728.91,-2600.96) 3750.64,-2600.96 ; 5012.99,-335.64 ccw(c5012.99,-380.22) 4981.47,-348.7 cw(c5012.99,-380.22) 5012.99,-335.64 ; 5012.99,-335.64 cw(c5012.99,-291.06) 4981.47,-322.58 ccw(c5012.99,-291.06) 5012.99,-335.64 ; 5037.13,-335.64 ccw(c5037.13,-404.36) 4988.54,-355.77 cw(c5037.13,-404.36) 5037.13,-335.64 ; 5037.13,-335.64 cw(c5037.13,-266.92) 4988.54,-315.51 ccw(c5037.13,-266.92) 5037.13,-335.64 ; P2.21@1642.25,-2342.29 ccw(c1642.25,-2304.5) 1668.97,-2331.22 cw(c1642.25,-2304.5) P2.21@1642.25,-2342.29 ; P2.21@1642.25,-2332.29 ccw(c1642.25,-2270.36) 1686.04,-2314.15 cw(c1642.25,-2270.36) P2.21@1642.25,-2332.29 ; P2.21@1656.78,-2356.82 cw(c1689.14,-2356.82) 1666.25,-2333.93 ccw(c1689.14,-2356.82) P2.21@1656.78,-2356.82 ; P2.21@1666.78,-2356.82 cw(c1723.28,-2356.82) 1683.33,-2316.86 ccw(c1723.28,-2356.82) P2.21@1666.78,-2356.82 ; 3386.43,-2560.12 cw(c3370.4,-2576.16) 3393.08,-2576.16 ccw(c3370.4,-2576.16) 3386.43,-2560.12 ; 3387.39,-2561.08 ccw(c3402.08,-2546.39) 3402.08,-2567.16 cw(c3402.08,-2546.39) 3387.39,-2561.08
  Bottom Layer w10: v2(3402.08,-2576.16) 3402.08,-2617.93 3483.37,-2699.22 3707.16,-2699.22 3750.64,-2655.74 v2(3750.64,-2622.69) ; 3402.08,-2597.89 ccw(c3380.35,-2597.89) 3395.71,-2582.52 cw(c3380.35,-2597.89) 3402.08,-2597.89 ; 3402.08,-2597.89 cw(c3423.81,-2597.89) 3408.44,-2582.52 ccw(c3423.81,-2597.89) 3402.08,-2597.89 ; 3750.64,-2644.41 ccw(c3728.91,-2644.41) 3744.28,-2629.05 cw(c3728.91,-2644.41) 3750.64,-2644.41 ; 3750.64,-2644.41 cw(c3772.37,-2644.41) 3757.01,-2629.05 ccw(c3772.37,-2644.41) 3750.64,-2644.41
HALL_A: P2.8
HALL_B: P2.7
HALL_C: P2.6
HB: P2.20 P8.3 R52.1 | length 7723.8
  Top Layer w10: R52.1@1933.48,-2169.52 1730.67,-2169.52 1591.38,-2308.8 1591.38,-2479.81 1615.84,-2504.26 1720.52,-2504.26 1754.41,-2538.15 3192.92,-2538.15 v2@3469.48,-2814.71 ; v2(3738.49,-2739.3) 3754.7,-2739.3 ; v3(5192.03,-437.58) 5192.03,-736.64 5110.74,-817.93 4908.07,-817.93 4471.07,-1254.94 4471.07,-1492.01 3933.93,-2029.14 3933.93,-2560.07 3754.7,-2739.3 ; 1910.32,-2169.52 ccw(c1910.32,-2148.32) 1925.31,-2163.31 cw(c1910.32,-2148.32) 1910.32,-2169.52 ; 1910.32,-2169.52 cw(c1910.32,-2190.71) 1925.31,-2175.73 ccw(c1910.32,-2190.71) 1910.32,-2169.52 ; 3754.7,-2739.3 ccw(c3754.7,-2749.4) 3746.13,-2744.06 cw(c3754.7,-2749.4) 3754.7,-2739.3 ; 3754.7,-2739.3 cw(c3754.7,-2729.19) 3746.13,-2734.54 ccw(c3754.7,-2729.19) 3754.7,-2739.3 ; 5192.03,-459.31 ccw(c5170.31,-459.31) 5185.67,-443.94 cw(c5170.31,-459.31) 5192.03,-459.31 ; 5192.03,-459.31 cw(c5213.76,-459.31) 5198.4,-443.94 ccw(c5213.76,-459.31) 5192.03,-459.31 ; 1599.58,-2300.61 ccw(c1555.79,-2256.82) 1617.72,-2256.82 cw(c1555.79,-2256.82) 1599.58,-2300.61 ; 1602.3,-2297.89 cw(c1642.25,-2337.84) 1642.25,-2281.34 ccw(c1642.25,-2337.84) 1602.3,-2297.89 ; 1616.65,-2283.53 ccw(c1589.94,-2256.82) 1627.72,-2256.82 cw(c1589.94,-2256.82) 1616.65,-2283.53 ; 1619.37,-2280.82 cw(c1642.25,-2303.7) 1642.25,-2271.34 ccw(c1642.25,-2303.7) 1619.37,-2280.82 ; P2.20@1642.25,-2242.29 ccw(c1642.25,-2204.5) 1668.97,-2231.22 cw(c1642.25,-2204.5) P2.20@1642.25,-2242.29 ; P2.20@1642.25,-2232.29 ccw(c1642.25,-2170.36) 1686.04,-2214.15 cw(c1642.25,-2170.36) P2.20@1642.25,-2232.29 ; P2.20@1656.78,-2256.82 cw(c1689.14,-2256.82) 1666.25,-2233.93 ccw(c1689.14,-2256.82) P2.20@1656.78,-2256.82 ; P2.20@1666.78,-2256.82 cw(c1723.28,-2256.82) 1683.33,-2216.86 ccw(c1723.28,-2256.82) P2.20@1666.78,-2256.82 ; 3452.67,-2797.91 cw(c3436.17,-2814.41) 3459.51,-2814.41 ccw(c3436.17,-2814.41) 3452.67,-2797.91 ; 3454.29,-2799.52 ccw(c3468.51,-2785.3) 3468.51,-2805.41 cw(c3468.51,-2785.3) 3454.29,-2799.52 ; v2@3738.49,-2740.3 ccw(c3738.49,-2703.57) 3764.46,-2729.54 cw(c3738.49,-2703.57) v2@3738.49,-2740.3 ; v2@3738.49,-2730.3 ccw(c3738.49,-2669.42) 3781.53,-2712.47 cw(c3738.49,-2669.42) v2@3738.49,-2730.3
  Bottom Layer w10: v2(3468.51,-2814.41) 3685.87,-2814.41 3738.48,-2761.81 v2(3738.49,-2739.3) ; P8.3@4950.7,-435.64 v3@5190.09,-435.64 ; 3490.24,-2814.41 ccw(c3490.24,-2836.14) 3474.87,-2820.78 cw(c3490.24,-2836.14) 3490.24,-2814.41 ; 3490.24,-2814.41 cw(c3490.24,-2792.69) 3474.87,-2808.05 ccw(c3490.24,-2792.69) 3490.24,-2814.41 ; 5012.99,-435.64 ccw(c5012.99,-480.22) 4981.47,-448.7 cw(c5012.99,-480.22) 5012.99,-435.64 ; 5012.99,-435.64 cw(c5012.99,-391.06) 4981.47,-422.58 ccw(c5012.99,-391.06) 5012.99,-435.64 ; 5037.13,-435.64 ccw(c5037.13,-504.36) 4988.54,-455.77 cw(c5037.13,-504.36) 5037.13,-435.64 ; 5037.13,-435.64 cw(c5037.13,-366.92) 4988.54,-415.51 ccw(c5037.13,-366.92) 5037.13,-435.64 ; v2@3732.13,-2745.66 cw(c3716.78,-2761) 3738.48,-2761 ccw(c3716.78,-2761) v2@3732.13,-2745.66 ; 3738.48,-2761.05 cw(c3760.24,-2761.05) 3744.85,-2745.66 ccw(c3760.24,-2761.05) 3738.48,-2761.05 ; 5165.62,-435.64 cw(c5165.62,-463.99) 5185.67,-443.94 ccw(c5165.62,-463.99) 5165.62,-435.64 ; 5174.99,-435.64 ccw(c5174.99,-420.53) 5185.67,-431.22 cw(c5174.99,-420.53) 5174.99,-435.64
HC: P2.19 P8.2 R51.1 | length 5736.2
  Top Layer w10: P2.19@1642.88,-2157.31 1718.82,-2081.37 R51.1@1933.22,-2081.37 1933.22,-2049.57 1955.97,-2026.81 2219.02,-2026.81 2578.91,-2386.71 3283.17,-2386.71 v1(3409.54,-2513.08) ; v1@3762.4,-2513.76 3846.96,-2429.2 3846.96,-2003.18 4397.15,-1452.98 4397.15,-1196.35 4844.18,-749.32 4844.18,-583.58 4892.12,-535.64 ; P8.2@4950.7,-535.64 4892.12,-535.64 ; 1910.05,-2081.37 ccw(c1910.05,-2060.17) 1925.04,-2075.16 cw(c1910.05,-2060.17) 1910.05,-2081.37 ; 1910.05,-2081.37 cw(c1910.05,-2102.57) 1925.04,-2087.58 ccw(c1910.05,-2102.57) 1910.05,-2081.37 ; 1933.22,-2060.17 ccw(c1954.41,-2060.17) 1939.43,-2075.16 cw(c1954.41,-2060.17) 1933.22,-2060.17 ; 1933.22,-2060.17 cw(c1912.02,-2060.17) 1927.01,-2075.16 ccw(c1912.02,-2060.17) 1933.22,-2060.17 ; 3395.89,-2499.42 ccw(c3409.54,-2485.76) 3409.54,-2505.08 cw(c3409.54,-2485.76) 3395.89,-2499.42 ; 3395.89,-2499.42 cw(c3382.23,-2513.08) 3401.54,-2513.08 ccw(c3382.23,-2513.08) 3395.89,-2499.42 ; 4892.12,-535.64 ccw(c4892.12,-520.55) 4906.28,-525.78 cw(c4892.12,-520.55) 4892.12,-535.64 ; 4892.12,-535.64 cw(c4892.12,-550.73) 4906.28,-545.5 ccw(c4892.12,-550.73) 4892.12,-535.64 ; P2.19@1642.25,-2142.29 ccw(c1642.25,-2104.5) 1668.97,-2131.22 cw(c1642.25,-2104.5) P2.19@1642.25,-2142.29 ; P2.19@1642.25,-2132.29 ccw(c1642.25,-2070.36) 1686.04,-2114.15 cw(c1642.25,-2070.36) P2.19@1642.25,-2132.29 ; P2.19@1656.78,-2156.82 cw(c1689.14,-2156.82) 1666.25,-2133.93 ccw(c1689.14,-2156.82) P2.19@1656.78,-2156.82 ; P2.19@1666.78,-2156.82 cw(c1723.28,-2156.82) 1683.33,-2116.86 ccw(c1723.28,-2156.82) P2.19@1666.78,-2156.82 ; v1@3760.57,-2505.09 ccw(c3760.57,-2479.73) 3778.5,-2497.66 cw(c3760.57,-2479.73) v1@3760.57,-2505.09 ; v1@3768.57,-2513.09 cw(c3781.85,-2513.09) 3772.46,-2503.7 ccw(c3781.85,-2513.09) v1@3768.57,-2513.09
  Bottom Layer w10: v1(3409.54,-2513.08) 3502.72,-2606.25 3697.61,-2606.25 3760.57,-2543.29 v1@3760.57,-2513.76 ; 3423.2,-2526.73 ccw(c3409.54,-2540.39) 3409.54,-2521.08 cw(c3409.54,-2540.39) 3423.2,-2526.73 ; 3423.2,-2526.73 cw(c3436.86,-2513.08) 3417.54,-2513.08 ccw(c3436.86,-2513.08) 3423.2,-2526.73 ; 3760.57,-2532.4 ccw(c3741.26,-2532.4) 3754.92,-2518.74 cw(c3741.26,-2532.4) 3760.57,-2532.4 ; 3760.57,-2532.4 cw(c3779.89,-2532.4) 3766.23,-2518.74 ccw(c3779.89,-2532.4) 3760.57,-2532.4
  other v1: 3760.57,-2513.09
HO1: D10.2 P1.23 R30.1 | length 3495.8
  Top Layer w10: R30.1@3192.94,-922.91 3192.94,-956.16 ; v2(3780.31,-1478.61) 3132.16,-1478.61 3068.76,-1415.21 3068.76,-1183.03 D10.2@3244.29,-1007.51 3192.94,-956.16 ; 3192.94,-956.16 ccw(c3168.07,-956.16) 3182.96,-936.24 cw(c3168.07,-956.16) 3192.94,-956.16 ; 3192.94,-956.16 cw(c3217.81,-956.16) 3202.91,-936.24 ccw(c3217.81,-956.16) 3192.94,-956.16 ; 3758.58,-1478.61 ccw(c3758.58,-1456.88) 3773.94,-1472.24 cw(c3758.58,-1456.88) 3758.58,-1478.61 ; 3758.58,-1478.61 cw(c3758.58,-1500.33) 3773.94,-1484.97 ccw(c3758.58,-1500.33) 3758.58,-1478.61 ; 3199.06,-1052.74 cw(c3244.29,-1097.97) 3244.29,-1034.01 ccw(c3244.29,-1097.97) 3199.06,-1052.74 ; 3199.06,-962.28 ccw(c3244.29,-917.05) 3244.29,-981.01 cw(c3244.29,-917.05) 3199.06,-962.28 ; 3213.31,-1038.48 ccw(c3188.24,-1013.42) 3223.7,-1013.42 cw(c3188.24,-1013.42) 3213.31,-1038.48 ; 3213.31,-976.54 cw(c3188.24,-1001.6) 3223.7,-1001.6 ccw(c3188.24,-1001.6) 3213.31,-976.54 ; 3216.13,-1035.67 cw(c3244.29,-1063.83) 3244.29,-1024.01 ccw(c3244.29,-1063.83) 3216.13,-1035.67 ; 3216.13,-979.35 ccw(c3244.29,-951.19) 3244.29,-991.01 cw(c3244.29,-951.19) 3216.13,-979.35
  Bottom Layer w10: P1.23@3642.25,-2556.82 3693.18,-2556.82 ; v2(3780.31,-1478.61) 3910.64,-1608.93 3910.64,-2284.3 3722.97,-2471.97 3722.97,-2527.02 3693.18,-2556.82 ; 3672.41,-2556.82 ccw(c3672.41,-2580.86) 3653.61,-2565.87 cw(c3672.41,-2580.86) 3672.41,-2556.82 ; 3672.41,-2556.82 cw(c3672.41,-2532.77) 3653.61,-2547.76 ccw(c3672.41,-2532.77) 3672.41,-2556.82 ; 3693.17,-2556.82 ccw(c3693.17,-2597.42) 3661.43,-2572.11 cw(c3693.17,-2597.42) 3693.17,-2556.82 ; 3693.17,-2556.82 cw(c3693.17,-2516.22) 3661.43,-2541.53 ccw(c3693.17,-2516.22) 3693.17,-2556.82 ; 3795.67,-1493.97 ccw(c3780.31,-1509.33) 3780.31,-1487.61 cw(c3780.31,-1509.33) 3795.67,-1493.97 ; 3795.67,-1493.97 cw(c3811.03,-1478.61) 3789.31,-1478.61 ccw(c3811.03,-1478.61) 3795.67,-1493.97
HO2: D8.2 P1.7 R28.1 | length 3074.3
  Top Layer w10: 1959.43,-1139.81 1959.43,-1424.09 2146.79,-1611.44 2713.02,-1611.44 3458.39,-2356.82 P1.7@3542.25,-2356.82 ; 3483.03,-2356.82 ccw(c3483.03,-2297.6) 3524.91,-2339.47 cw(c3483.03,-2297.6) 3483.03,-2356.82 ; 3483.03,-2356.82 cw(c3483.03,-2416.03) 3524.91,-2374.16 ccw(c3483.03,-2416.03) 3483.03,-2356.82 ; 3507.18,-2356.82 ccw(c3507.18,-2321.74) 3531.98,-2346.54 cw(c3507.18,-2321.74) 3507.18,-2356.82 ; 3507.18,-2356.82 cw(c3507.18,-2391.89) 3531.98,-2367.09 ccw(c3507.18,-2391.89) 3507.18,-2356.82
  Top Layer w20: 1959.43,-1139.81 D8.2@2033.81,-1065.43 ; D8.2@2046.11,-1053.13 R28.1@2046.11,-965.39 ; 2046.11,-993.52 ccw(c2017.97,-993.52) 2037.87,-973.63 cw(c2017.97,-993.52) 2046.11,-993.52 ; 2046.11,-993.52 cw(c2074.24,-993.52) 2054.35,-973.63 ccw(c2074.24,-993.52) 2046.11,-993.52 ; 1997.12,-1102.12 cw(c2033.81,-1138.82) 2033.81,-1086.92 ccw(c2033.81,-1138.82) 1997.12,-1102.12 ; D8.2@2011.37,-1087.87 ccw(c1994.84,-1071.33) 2018.22,-1071.33 cw(c1994.84,-1071.33) D8.2@2011.37,-1087.87 ; D8.2@2022.79,-1048.5 ccw(c1966.49,-992.2) 2046.11,-992.2 cw(c1966.49,-992.2) D8.2@2022.79,-1048.5
HO3: D3.2 P1.20 R26.1 | length 4393.7
  Top Layer w20: R26.1@1010.51,-909.43 1032.41,-931.33 D3.2@1032.41,-988.88 1085.78,-1042.24 1085.78,-1504.09 1125.9,-1544.22 1423.58,-1544.22 v2(1456.96,-1577.6) ; 1032.41,-945.33 ccw(c1070.05,-945.33) 1043.43,-971.95 cw(c1070.05,-945.33) 1032.41,-945.33 ; 1032.41,-945.33 cw(c994.77,-945.33) 1021.38,-971.95 ccw(c994.77,-945.33) 1032.41,-945.33 ; R26.1@1005.62,-917.67 cw(c940.95,-982.34) 1032.41,-982.34 ccw(c940.95,-982.34) R26.1@1005.62,-917.67 ; R26.1@1013.86,-921.09 cw(c1013.86,-941.14) 1028.04,-926.96 ccw(c1013.86,-941.14) R26.1@1013.86,-921.09 ; R26.1@1019.76,-903.53 cw(c989.24,-934.06) 1032.41,-934.06 ccw(c989.24,-934.06) R26.1@1019.76,-903.53 ; R26.1@1025.29,-911.71 ccw(c1044.79,-915.59) 1030.73,-929.65 cw(c1044.79,-915.59) R26.1@1025.29,-911.71 ; D3.2@1032.41,-1010.37 cw(c1032.41,-1062.27) 1069.1,-1025.57 ccw(c1032.41,-1062.27) D3.2@1032.41,-1010.37 ; D3.2@1048,-994.78 ccw(c1071.38,-994.78) 1054.85,-1011.31 cw(c1071.38,-994.78) D3.2@1048,-994.78
  Bottom Layer w10: v2(1456.96,-1577.6) 1477.1,-1557.47 1788.12,-1557.47 2437,-2206.35 3591.78,-2206.35 P1.20@3642.25,-2256.82 ; 1472.33,-1562.24 ccw(c1487.69,-1577.6) 1465.96,-1577.6 cw(c1487.69,-1577.6) 1472.33,-1562.24 ; 1472.33,-1562.24 cw(c1456.96,-1546.88) 1456.96,-1568.6 ccw(c1456.96,-1546.88) 1472.33,-1562.24 ; 3600.38,-2214.94 ccw(c3642.25,-2173.07) 3642.25,-2232.29 cw(c3642.25,-2173.07) 3600.38,-2214.94 ; 3600.38,-2214.94 cw(c3558.51,-2256.82) 3617.72,-2256.82 ccw(c3558.51,-2256.82) 3600.38,-2214.94 ; 3617.45,-2232.02 ccw(c3642.25,-2207.22) 3642.25,-2242.29 cw(c3642.25,-2207.22) 3617.45,-2232.02 ; 3617.45,-2232.02 cw(c3592.65,-2256.82) 3627.72,-2256.82 ccw(c3592.65,-2256.82) 3617.45,-2232.02
LED1: LED1.1 P2.14 | length 3076
  Top Layer w10: P2.14@1542.25,-3056.82 1621.34,-3135.91 3866.88,-3135.91 4002.57,-3000.22 LED1.1@4106.77,-3000.22 ; 1567.05,-3081.62 ccw(c1542.25,-3106.42) 1542.25,-3071.34 cw(c1542.25,-3106.42) 1567.05,-3081.62 ; 1567.05,-3081.62 cw(c1591.85,-3056.82) 1556.78,-3056.82 ccw(c1591.85,-3056.82) 1567.05,-3081.62 ; 1584.12,-3098.69 ccw(c1542.25,-3140.56) 1542.25,-3081.34 cw(c1542.25,-3140.56) 1584.12,-3098.69 ; 1584.12,-3098.69 cw(c1625.99,-3056.82) 1566.78,-3056.82 ccw(c1625.99,-3056.82) 1584.12,-3098.69 ; 4066.57,-3000.22 ccw(c4066.57,-2960.01) 4094.99,-2988.44 cw(c4066.57,-2960.01) 4066.57,-3000.22 ; 4066.57,-3000.22 cw(c4066.57,-3040.42) 4094.99,-3011.99 ccw(c4066.57,-3040.42) 4066.57,-3000.22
